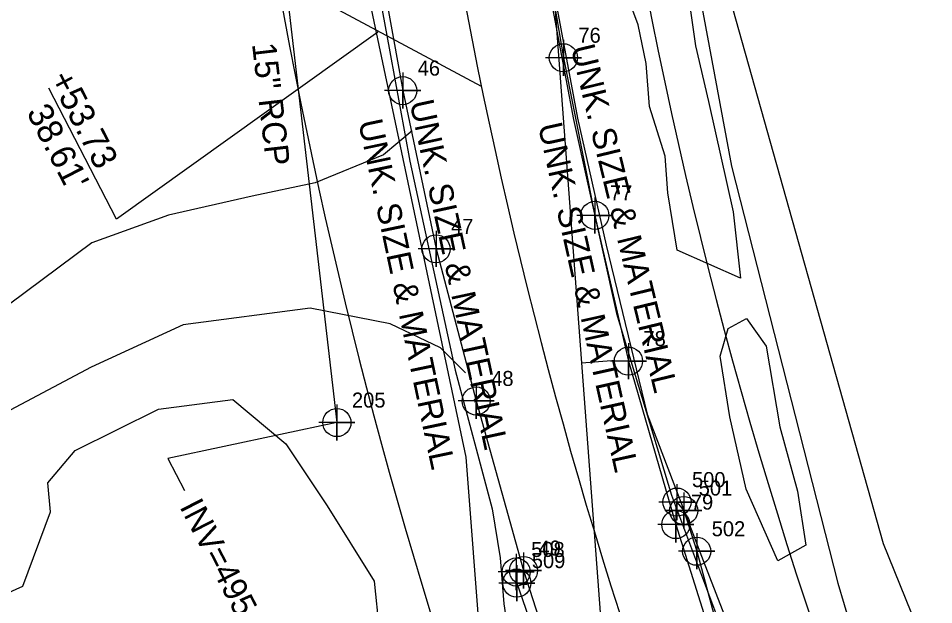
# Model space of a CAD drawing. Extents: x 1534145 to 1537876, y 509021 to 513201.
# Drawn here: x 1535965.3 to 1536117.6, y 511855.4 to 511953.1 of the extents above; entities that cross this region are included whole.
import ezdxf

# ---------------------------------------------------------------- set-up
doc = ezdxf.new("R2010")
doc.units = 0
for name, color, linetype in [('Exist Guardrail', 7, 'Continuous'), ('Exist Guardrail Cogo Number', 7, 'Continuous'), ('Exist Guardrail Cogo Point CELL', 7, 'Continuous'), ('Exist Horizontal Alignment', 7, 'Continuous'), ('Exist Horizontal Baseline Alignment', 7, 'Continuous'), ('Exist Horizontal Baseline Alignment Tick small', 7, 'Continuous'), ('Exist Property Tie Line', 7, 'Continuous'), ('Exist Property Tie Line Leader', 7, 'Continuous'), ('Exist Property Tie Line Text', 7, 'Continuous'), ('Exist Right of Way Line', 7, 'Continuous'), ('Exist Roads EOP', 7, 'Continuous'), ('Exist Roads EOP Cogo Number', 7, 'Continuous'), ('Exist Roads EOP Cogo Point CELL', 7, 'Continuous'), ('Exist Roads Soil', 7, 'Continuous'), ('Exist Structure Minor Pipes RCP 15 Inch', 7, 'Continuous'), ('Exist Structure Minor Pipes RCP 15 Inch Cogo Number', 7, 'Continuous'), ('Exist Structure Minor Pipes RCP 15 Inch Cogo Point CELL', 7, 'Continuous'), ('Exist Structure Minor Pipes RCP 15 Inch Invert', 7, 'Continuous'), ('Exist Structure Minor Pipes RCP 15 Inch Text', 7, 'Continuous'), ('Exist Utilities Telephone UG Cable', 7, 'Continuous'), ('Exist Utilities Telephone UG Cable Text', 7, 'Continuous'), ('Exist Utilities Telephone UG FO SUE', 7, 'Continuous'), ('Exist Utilities Telephone UG FO SUE Text', 7, 'Continuous'), ('Exist Utilities TV UG Cable', 7, 'Continuous'), ('Exist Utilities TV UG Cable Text', 7, 'Continuous'), ('Exist Utilities Water UG Line SUE', 7, 'Continuous'), ('Exist Vegetation Hedge Row', 7, 'Continuous'), ('Exist Vegetation Woods Line', 7, 'Continuous')]:
    doc.layers.add(name, color=color, linetype=linetype)

msp = doc.modelspace()

# ---------------------------------------------------------------- linework, layer by layer
at = {"layer": 'Exist Guardrail'}
for points in [[(1536074.85, 511872.53), (1536075.97, 511871.12), (1536078.13, 511864.34), (1536081.93, 511850.29), (1536088.14, 511829.73), (1536094.99, 511810.79), (1536101.36, 511793.67), (1536106.71, 511780.22)], [(1536048.09, 511860.89), (1536048.2, 511859.04), (1536054.52, 511840.77), (1536061.19, 511823.13), (1536067.99, 511805.64), (1536075.37, 511787.74), (1536083.08, 511770.09)]]:
    msp.add_lwpolyline(points, dxfattribs=at)
at = {"layer": 'Exist Guardrail Cogo Point CELL'}
for points in [[(1536074.85, 511875.53), (1536074.85, 511869.53), (1536074.85, 511872.53), (1536077.85, 511872.53), (1536071.85, 511872.53)], [(1536075.97, 511874.12), (1536075.97, 511868.12), (1536075.97, 511871.12), (1536078.97, 511871.12), (1536072.97, 511871.12)], [(1536078.13, 511867.34), (1536078.13, 511861.34), (1536078.13, 511864.34), (1536081.13, 511864.34), (1536075.13, 511864.34)], [(1536048.09, 511863.89), (1536048.09, 511857.89), (1536048.09, 511860.89), (1536051.09, 511860.89), (1536045.09, 511860.89)], [(1536048.2, 511862.04), (1536048.2, 511856.04), (1536048.2, 511859.04), (1536051.2, 511859.04), (1536045.2, 511859.04)]]:
    msp.add_lwpolyline(points, dxfattribs=at)
for centre in [(1536074.85, 511872.53), (1536075.97, 511871.12), (1536078.13, 511864.34), (1536048.09, 511860.89), (1536048.2, 511859.04)]:
    msp.add_circle(centre, 2.34, dxfattribs=at)
at = {"layer": 'Exist Horizontal Alignment'}
msp.add_arc((1536874.85, 512113.15), 850, 183.46397, 223.9944, dxfattribs=at)
at = {"layer": 'Exist Horizontal Baseline Alignment'}
msp.add_line((1536014.28, 512494.06), (1536066.28, 511797.6), dxfattribs=at)
at = {"layer": 'Exist Horizontal Baseline Alignment Tick small'}
msp.add_line((1536058.95, 511895.73), (1536063.94, 511896.1), dxfattribs=at)
at = {"layer": 'Exist Property Tie Line'}
msp.add_line((1536042.31, 511941.76), (1536008.28, 511960), dxfattribs=at)
at = {"layer": 'Exist Property Tie Line Leader'}
msp.add_lwpolyline([(1536025.05, 511950.77), (1535981.61, 511919.65), (1535970.35, 511941.47)], dxfattribs=at)
at = {"layer": 'Exist Right of Way Line'}
for radius, end in [(820, 207.24292), (880, 223.9944)]:
    msp.add_arc((1536874.85, 512113.15), radius, 183.46397, end, dxfattribs=at)
at = {"layer": 'Exist Roads EOP'}
for points in [[(1536017.13, 512355.26), (1536014.26, 512300.49), (1536012.14, 512243.65), (1536010.77, 512187), (1536010.94, 512130.32), (1536011.88, 512103.45), (1536013.15, 512076.44), (1536015.19, 512049.65), (1536017.8, 512022.41), (1536021.13, 511995.47), (1536025, 511968.91), (1536024.58, 511966.83), (1536029.21, 511941.05), (1536034.76, 511914.7), (1536041.44, 511889.37), (1536049.32, 511861.12), (1536057.39, 511835.94), (1536066.82, 511810.74), (1536075.96, 511787.93), (1536078.27, 511780.03), (1536082.69, 511771.9), (1536083.54, 511771.14)], [(1536047.73, 511997.73), (1536051.29, 511973.89), (1536055.95, 511946.53), (1536061.19, 511920.28), (1536066.77, 511896.01), (1536074.66, 511868.78), (1536082.44, 511844.1), (1536091.17, 511819.72), (1536099.54, 511796.92), (1536105.63, 511781.95), (1536105.4, 511780.92)]]:
    msp.add_lwpolyline(points, dxfattribs=at)
at = {"layer": 'Exist Roads EOP Cogo Point CELL'}
for points in [[(1536055.95, 511949.53), (1536055.95, 511943.53), (1536055.95, 511946.53), (1536058.95, 511946.53), (1536052.95, 511946.53)], [(1536029.21, 511944.05), (1536029.21, 511938.05), (1536029.21, 511941.05), (1536032.21, 511941.05), (1536026.21, 511941.05)], [(1536061.19, 511923.28), (1536061.19, 511917.28), (1536061.19, 511920.28), (1536064.19, 511920.28), (1536058.19, 511920.28)], [(1536034.76, 511917.7), (1536034.76, 511911.7), (1536034.76, 511914.7), (1536037.76, 511914.7), (1536031.76, 511914.7)], [(1536066.77, 511899.01), (1536066.77, 511893.01), (1536066.77, 511896.01), (1536069.77, 511896.01), (1536063.77, 511896.01)], [(1536041.44, 511892.37), (1536041.44, 511886.37), (1536041.44, 511889.37), (1536044.44, 511889.37), (1536038.44, 511889.37)], [(1536074.66, 511871.78), (1536074.66, 511865.78), (1536074.66, 511868.78), (1536077.66, 511868.78), (1536071.66, 511868.78)], [(1536049.32, 511864.12), (1536049.32, 511858.12), (1536049.32, 511861.12), (1536052.32, 511861.12), (1536046.32, 511861.12)]]:
    msp.add_lwpolyline(points, dxfattribs=at)
for centre in [(1536055.95, 511946.53), (1536029.21, 511941.05), (1536061.19, 511920.28), (1536034.76, 511914.7), (1536066.77, 511896.01), (1536041.44, 511889.37), (1536074.66, 511868.78), (1536049.32, 511861.12)]:
    msp.add_circle(centre, 2.34, dxfattribs=at)
at = {"layer": 'Exist Roads Soil'}
for points in [[(1536030.79, 511934.33), (1536026.01, 511930.37), (1536014.66, 511925.69), (1536004.17, 511923.48), (1535990.27, 511920.3), (1535977.46, 511915.68), (1535960.89, 511903.4), (1535945.79, 511890.43), (1535921.29, 511869.12), (1535896.75, 511850.95), (1535874.6, 511838.39), (1535844.2, 511825.42), (1535813.98, 511815.68)], [(1536039.65, 511894.07), (1536035.49, 511898.22), (1536027.12, 511902.22), (1536013.83, 511904.85), (1535992.7, 511902.05), (1535977.38, 511894.99), (1535963.9, 511887.86), (1535950.34, 511877.24), (1535946.17, 511873.71), (1535934.26, 511863.42), (1535914.4, 511847.98), (1535895.78, 511835.37), (1535887.36, 511829.99), (1535870.29, 511822.32), (1535859.15, 511817.73), (1535835.74, 511809.4), (1535826.87, 511806.69), (1535817.88, 511804.05)]]:
    msp.add_lwpolyline(points, dxfattribs=at)
at = {"layer": 'Exist Structure Minor Pipes RCP 15 Inch'}
msp.add_line((1536008.33, 511971.15), (1536018.27, 511885.77), dxfattribs=at)
at = {"layer": 'Exist Structure Minor Pipes RCP 15 Inch Cogo Point CELL'}
msp.add_lwpolyline([(1536018.27, 511888.77), (1536018.27, 511882.77), (1536018.27, 511885.77), (1536021.27, 511885.77), (1536015.27, 511885.77)], dxfattribs=at)
msp.add_circle((1536018.27, 511885.77), 2.34, dxfattribs=at)
at = {"layer": 'Exist Structure Minor Pipes RCP 15 Inch Invert'}
msp.add_lwpolyline([(1536018.27, 511885.77), (1535990.13, 511879.79), (1535992.88, 511874.46)], dxfattribs=at)
at = {"layer": 'Exist Utilities Telephone UG Cable'}
for p, q in [((1536054.94, 511954.63), (1536058.31, 511936.44)), ((1536058.31, 511936.44), (1536063.07, 511915.29)), ((1536063.07, 511915.29), (1536069.88, 511887.18)), ((1536069.88, 511887.18), (1536079.23, 511862.8)), ((1536079.23, 511862.8), (1536087.05, 511842.69))]:
    msp.add_line(p, q, dxfattribs=at)
msp.add_lwpolyline([(1536007.51, 512112.19), (1536011.33, 512050.44), (1536011.99, 512042.85), (1536022.09, 511963.64), (1536039.72, 511880.01), (1536042.17, 511848.19), (1536065.07, 511790.17)], dxfattribs=at)
at = {"layer": 'Exist Utilities Telephone UG FO SUE'}
for p, q in [((1536076.66, 511967.84), (1536083.9, 511928.45)), ((1536024, 511964.28), (1536027.07, 511947.5)), ((1536027.07, 511947.5), (1536030.42, 511929.3)), ((1536030.42, 511929.3), (1536037.93, 511894.49)), ((1536083.9, 511928.45), (1536101.61, 511859.02)), ((1536037.93, 511894.49), (1536044.1, 511871.38)), ((1536044.1, 511871.38), (1536045.43, 511863.23)), ((1536045.43, 511863.23), (1536046.04, 511855.56)), ((1536101.61, 511859.02), (1536108.36, 511836.25)), ((1536046.04, 511855.56), (1536047.11, 511848.8))]:
    msp.add_line(p, q, dxfattribs=at)
at = {"layer": 'Exist Utilities TV UG Cable'}
for p, q in [((1536050.61, 511973.51), (1536057.64, 511936.23)), ((1536057.64, 511936.23), (1536064.8, 511903.93)), ((1536064.8, 511903.93), (1536073.94, 511873.69)), ((1536073.94, 511873.69), (1536082.5, 511850.93))]:
    msp.add_line(p, q, dxfattribs=at)
at = {"layer": 'Exist Utilities Water UG Line SUE'}
for p, q in [((1536080.14, 511968.83), (1536109.14, 511865.62)), ((1536109.14, 511865.62), (1536126.22, 511823.79))]:
    msp.add_line(p, q, dxfattribs=at)
at = {"layer": 'Exist Vegetation Hedge Row'}
for points in [[(1536064.79, 511968.66), (1536066.75, 511976.15), (1536070.41, 511978.14), (1536075.56, 511976.19), (1536076.47, 511970.89), (1536076.24, 511963.6), (1536076.95, 511955.49), (1536077.91, 511948.53), (1536080.07, 511939.23), (1536084.19, 511920.89), (1536085.42, 511909.81), (1536074.87, 511914.5), (1536073.32, 511924.05), (1536072.91, 511930.13), (1536070.3, 511938.43), (1536069.72, 511945.57), (1536068.39, 511952.02), (1536066.66, 511956.69), (1536064.92, 511961.94), (1536064.79, 511968.66)], [(1536082.02, 511896.84), (1536083.38, 511901.46), (1536086.41, 511903.09), (1536089.7, 511898.51), (1536091.99, 511885.08), (1536094.9, 511874.33), (1536096.32, 511865.35), (1536091.61, 511862.76), (1536086.37, 511874.7), (1536083.65, 511886.74), (1536082.02, 511896.84)]]:
    msp.add_lwpolyline(points, dxfattribs=at)
at = {"layer": 'Exist Vegetation Woods Line'}
msp.add_lwpolyline([(1535954.04, 511853.16), (1535966.02, 511858.51), (1535970.6, 511870.91), (1535970.15, 511875.74), (1535974.71, 511881.1), (1535988.59, 511888.03), (1536000.97, 511889.59), (1536009.77, 511882.21), (1536016.62, 511871.88), (1536024.49, 511859.38), (1536025.31, 511851.26), (1536029.33, 511842.5), (1536032.33, 511832.43), (1536038.1, 511823.16), (1536040.7, 511813.2), (1536045, 511805.29), (1536048.58, 511798.25), (1536049.61, 511787.84), (1536052.62, 511782.04), (1536051.19, 511773.44), (1536046.44, 511770.73), (1536040.52, 511767.51), (1536036.36, 511759.53)], dxfattribs=at)

# ---------------------------------------------------------------- texts
at = {"layer": 'Exist Guardrail Cogo Number'}
for s, p in [('500', (1536077.35, 511875.03)), ('501', (1536078.47, 511873.62)), ('502', (1536080.63, 511866.84)), ('508', (1536050.59, 511863.39)), ('509', (1536050.7, 511861.54))]:
    msp.add_text(s, height=2.5, dxfattribs=at).set_placement(p)
at = {"layer": 'Exist Property Tie Line Text'}
for s, rotation, p in [('+53.73', 297.2824, (1535970.35, 511943.07)), ("38.61'", 297.234, (1535966.54, 511937.46))]:
    msp.add_text(s, height=4.2, rotation=rotation, dxfattribs=at).set_placement(p)
at = {"layer": 'Exist Roads EOP Cogo Number'}
for s, p in [('76', (1536058.45, 511949.03)), ('46', (1536031.71, 511943.55)), ('77', (1536063.69, 511922.78)), ('47', (1536037.26, 511917.2)), ('78', (1536069.27, 511898.51)), ('48', (1536043.94, 511891.87)), ('79', (1536077.16, 511871.28)), ('49', (1536051.82, 511863.62))]:
    msp.add_text(s, height=2.5, dxfattribs=at).set_placement(p)
at = {"layer": 'Exist Structure Minor Pipes RCP 15 Inch Cogo Number'}
msp.add_text('205', height=2.5, dxfattribs=at).set_placement((1536020.77, 511888.27))
at = {"layer": 'Exist Structure Minor Pipes RCP 15 Inch Invert'}
msp.add_text("INV=495.39'", height=4, rotation=297.2825, dxfattribs=at).set_placement((1535992.02, 511871.77))
at = {"layer": 'Exist Structure Minor Pipes RCP 15 Inch Text'}
msp.add_text('15" RCP', height=4, rotation=276.6455, dxfattribs=at).set_placement((1536004.13, 511948.82))
at = {"layer": 'Exist Utilities Telephone UG Cable Text'}
for rotation, p in [(283.6072, (1536057.15, 511948.24)), (281.9085, (1536021.81, 511935.87))]:
    msp.add_text('UNK. SIZE & MATERIAL', height=4, rotation=rotation, dxfattribs=at).set_placement(p)
at = {"layer": 'Exist Utilities Telephone UG FO SUE Text'}
msp.add_text('UNK. SIZE & MATERIAL', height=4, rotation=282.1827, dxfattribs=at).set_placement((1536030.35, 511939.1))
at = {"layer": 'Exist Utilities TV UG Cable Text'}
msp.add_text('UNK. SIZE & MATERIAL', height=4, rotation=282.5063, dxfattribs=at).set_placement((1536051.71, 511935.26))

doc.saveas('drawing.dxf')
